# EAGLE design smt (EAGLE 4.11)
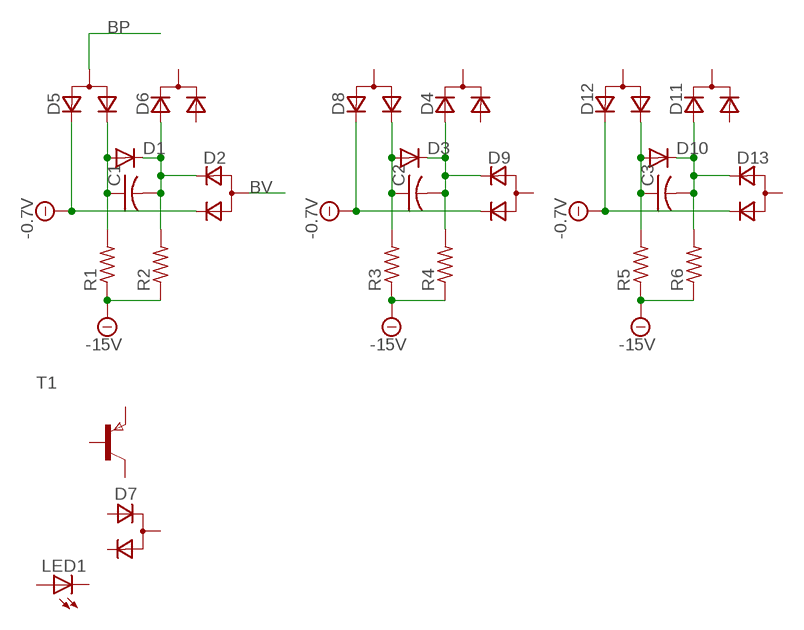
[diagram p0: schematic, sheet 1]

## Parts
C1  C-USC0603  [C0603]
C2  C-USC0603  [C0603]
C3  C-USC0603  [C0603]
D1  DIODE-SOD323-R  [SOD323-R]
D2  D_2CSOT323  [SOT323]
D3  DIODE-SOD323-R  [SOD323-R]
D4  D_2ASOT323  [SOT323]
D5  D_2CSOT323  [SOT323]
D6  D_2ASOT323  [SOT323]
D7  D_ACACSOT323  [SOT323]
D8  D_2CSOT323  [SOT323]
D9  D_2CSOT323  [SOT323]
D10  DIODE-SOD323-R  [SOD323-R]
D11  D_2ASOT323  [SOT323]
D12  D_2CSOT323  [SOT323]
D13  D_2CSOT323  [SOT323]
LED1  LED  [SMARTLED-TTW]
R1  R-US_R0603  [R0603]
R2  R-US_R0603  [R0603]
R3  R-US_R0603  [R0603]
R4  R-US_R0603  [R0603]
R5  R-US_R0603  [R0603]
R6  R-US_R0603  [R0603]
T1  PNPSOT323  [SOT323]

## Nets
-1V: D2.3(C2) D5.2(C1) D8.2(C1) D9.3(C2) D12.2(C1) D13.3(C2) ; supply symbol labelled -0.7V
-15V: R1.1 R2.1 R3.1 R4.1 R5.1 R6.1
BP: D5.1(A)
BV: D2.1(A)
N$1: C1.1 D1.A D5.3(C2) R1.2
N$2: C1.2 D1.C D2.2(C1) D6.2(A1) R2.2
N$3: C2.1 D3.A D8.3(C2) R3.2
N$4: C2.2 D3.C D4.2(A1) D9.2(C1) R4.2
N$5: C3.1 D10.A D12.3(C2) R5.2
N$6: C3.2 D10.C D11.2(A1) D13.2(C1) R6.2
Unconnected: D4.1(C) D4.3(A2) D6.1(C) D6.3(A2) D7.1(CA) D7.2(C) D7.3(A) D8.1(A) D9.1(A) D11.1(C) D11.3(A2) D12.1(A) D13.1(A) LED1.A@1(A) LED1.C@1(C) T1.1(C) T1.2(B) T1.3(E)

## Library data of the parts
C1-C3 = rcl:C-US: CAPACITOR, American symbol
D1 D3 D10 = diode:DIODE-: DIODE
D2 D5 D8 D9 D12 D13 = zetex:D_2C: Dual DIODE
D4 D6 D11 = zetex:D_2A: Dual DIODE
D7 = zetex:D_ACAC: Dual DIODE
LED1 = led:LED: LED
R1-R6 = rcl:R-US_: RESISTOR, American symbol
T1 = zetex:PNPSOT323: PNP TRANSISTOR

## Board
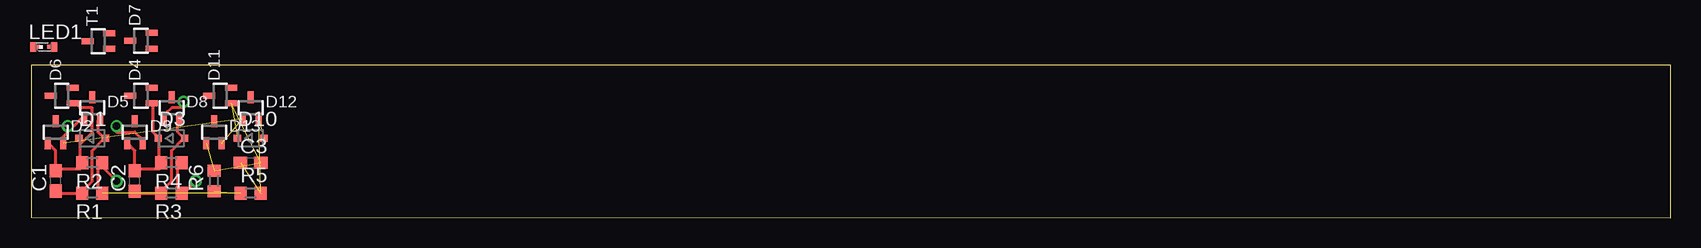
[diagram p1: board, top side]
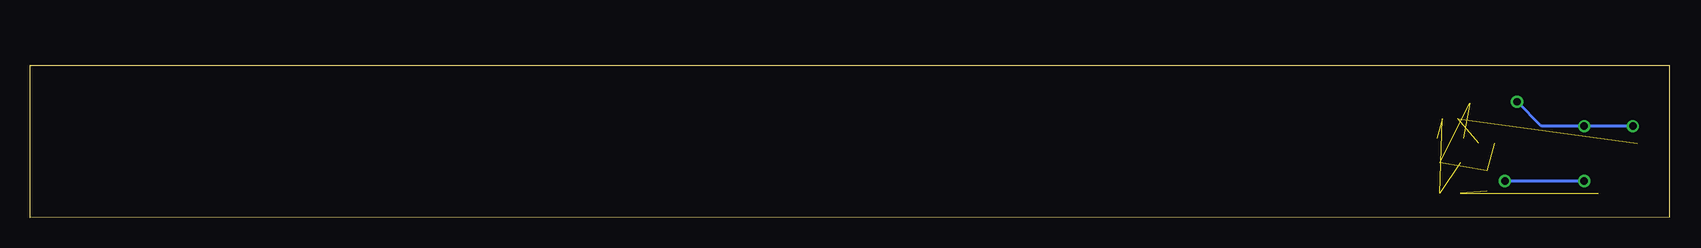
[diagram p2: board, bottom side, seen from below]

Size 136.65 x 12.71 mm. Coordinates in mm from the lower left corner, seen from the top.
Outline: 136.65,0 136.65,12.68 0,12.71 0,0.02 136.65,0
Copper layers (1*16): Top 0.035mm / dielectric 1.5mm / Bottom 0.035mm
Design rules "olimex8mil": minimum track width 10mil, minimum drill 24mil, track to track 8mil, track to pad 8mil, pad to pad 8mil, via to via 8mil, smd to smd 8mil, copper to edge 40mil, drill to drill 10mil, minimum pad ring 10mil, minimum via ring 8mil, stop-mask expansion 0mil, vias tented up to drill 0mil, thermal gap 10mil

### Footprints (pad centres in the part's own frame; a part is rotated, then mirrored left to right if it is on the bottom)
C0603 = smd 1.1 x 1: 1 -0.85,0; 2 0.85,0
SOD323-R = smd 0.6 x 0.6: A 1.1,0; C -1.1,0
SOT323 = smd 0.5 x 1: 1 0,0.9; 2 -0.65,-0.9; 3 0.65,-0.9
SMARTLED-TTW = smd 0.8 x 0.5: A 0,-0.875; C 0,0.875 | smd 0.35 x 0.35: A@1 0,-0.5; C@1 0,0.5
R0603 = smd 1 x 1.1: 1 -0.85,0; 2 0.85,0

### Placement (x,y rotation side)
C1  2.02,3.06 90 top
C2  8.62,3.04 90 top
C3  18.28,4.57 0 top
D1  5.07,6.6 0 top
D2  2.02,7.11 0 top
D3  11.67,6.6 0 top
D4  9.13,10.15 90 top
D5  5.07,9.14 0 top
D6  2.53,10.15 90 top
D7  9.13,14.73 90 top
D8  11.67,9.14 0 top
D9  8.62,7.11 0 top
D10  18.28,6.6 0 top
D11  15.74,10.15 90 top
D12  18.28,9.14 0 top
D13  15.23,7.11 0 top
LED1  1,14.22 270 top
R1  5.07,2.03 180 top
R2  5.07,4.57 180 top
R3  11.67,2.03 180 top
R4  11.67,4.57 180 top
R5  18.28,2.03 0 top
R6  15.23,3.04 90 top
T1  5.58,14.7 90 top

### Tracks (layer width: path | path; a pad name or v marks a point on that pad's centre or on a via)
-1V  (via drill 0.61)  (2 unrouted)
  Top 0.254: 3.54,7.62 4.56,8.63 D5.2 | 3.54,7.62 2.53,6.6 D2.3 | v7.1,7.62 7.1,7.11 8.62,7.11 9.13,6.6 D9.3 | 3.54,7.62 v3.04,7.62 | v12.69,9.65 12.69,9.14 11.67,9.14 11.16,8.63 D8.2
  Bottom 0.254: v3.04,7.62 v7.1,7.62 10.66,7.62 v12.69,9.65
-15V  (via drill 0.61)  (2 unrouted)
  Top 0.254: R1.1 5.58,2.54 5.58,4.06 R2.1 6.08,4.06 v7.1,3.04 | R4.1 12.18,4.06 12.18,2.54 R3.1 12.69,2.03 v13.7,3.04
  Bottom 0.254: v7.1,3.04 v13.7,3.04
N$1
  Top 0.254: 6.08,6.6 5.58,7.11 5.58,8.12 D5.3 | 6.08,6.6 D1.A 6.08,6.6 | C1.1 2.02,2.03 4.05,2.03 R1.2 4.56,2.54 5.07,3.04 5.07,5.58 6.08,6.6
N$2
  Top 0.254: 2.02,4.06 2.02,5.58 1.51,6.09 D2.2 | 2.02,4.06 C1.2 2.02,4.06 | 4.05,6.09 4.05,5.08 R2.2 4.05,4.06 2.02,4.06 | 4.05,6.09 4.05,6.6 D1.C | 4.05,6.09 5.07,7.11 5.07,9.14 4.05,9.14 3.54,9.65 D6.2
N$3
  Top 0.254: 12.69,6.6 12.18,7.11 12.18,8.12 D8.3 | 12.69,6.6 D3.A 12.69,6.6 | C2.1 8.62,2.03 10.66,2.03 R3.2 11.16,2.54 11.67,3.04 11.67,5.58 12.69,6.6
N$4
  Top 0.254: 8.62,4.06 8.62,5.58 8.12,6.09 D9.2 | 8.62,4.06 C2.2 8.62,4.06 | 10.66,6.6 10.66,5.08 R4.2 10.66,4.06 8.62,4.06 | 10.66,6.6 D3.C 10.66,6.6 | 10.66,6.6 10.15,7.11 10.15,9.65 D4.2
N$5  (3 unrouted)
N$6  (4 unrouted)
